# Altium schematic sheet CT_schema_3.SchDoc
size 287 x 169 mm
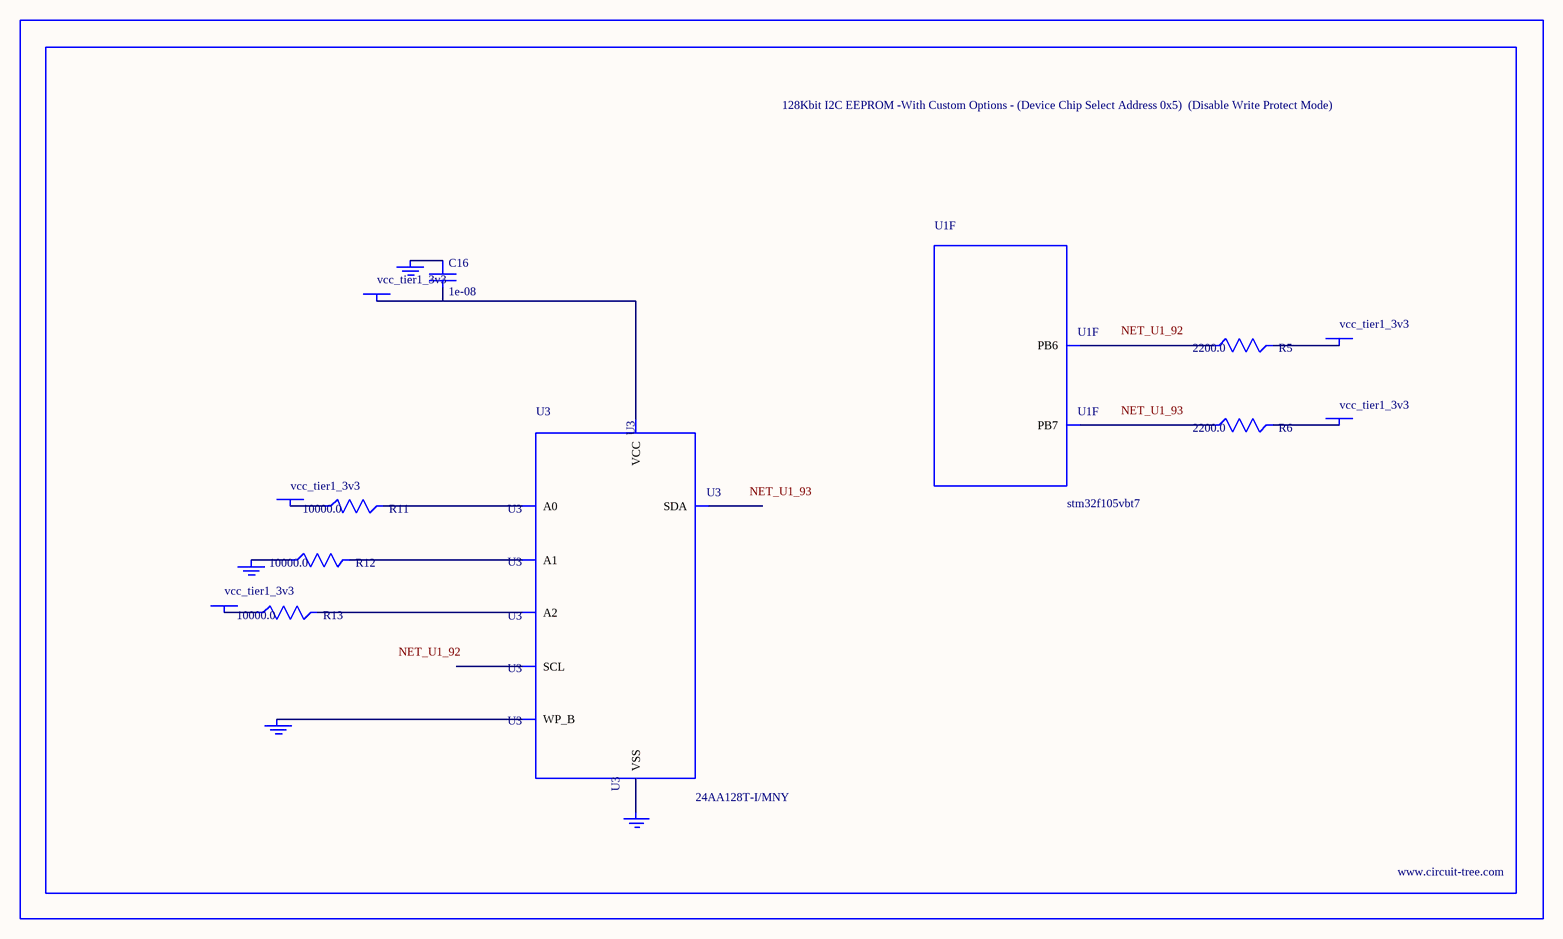
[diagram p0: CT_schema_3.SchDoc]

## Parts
BORDER2  (no value)
C16  1e-08  [C0402]
GND_INSTANCE_2_0  (no value)
GND_INSTANCE_2_1  (no value)
GND_INSTANCE_2_2  (no value)
GND_INSTANCE_2_3  (no value)
POWER_INSTANCE_2_0  vcc_tier1_3v3
POWER_INSTANCE_2_1  vcc_tier1_3v3
POWER_INSTANCE_2_2  vcc_tier1_3v3
POWER_INSTANCE_2_3  vcc_tier1_3v3
POWER_INSTANCE_2_4  vcc_tier1_3v3
R5  2200.0  [R0603]
R6  2200.0  [R0603]
R11  10000.0  [R0603]
R12  10000.0  [R0603]
R13  10000.0  [R0603]
U1  stm32f105vbt7  [LQFP100]  (part F of 10)
U3  24AA128T-I/MNY  [TDFN-8/6MM]

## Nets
NetC16_1: C16.1 GND_INSTANCE_2_2.0(GND)
NetC16_2: C16.2 POWER_INSTANCE_2_2.0(PWR) U3.8(VCC)
NetGND_INSTANCE_2_0_0: GND_INSTANCE_2_0.0(GND) R12.1
NetGND_INSTANCE_2_1_0: GND_INSTANCE_2_1.0(GND) U3.7(WP_B)
NetGND_INSTANCE_2_3_0: GND_INSTANCE_2_3.0(GND) U3.4(VSS)
NetPOWER_INSTANCE_2_0_0: POWER_INSTANCE_2_0.0(PWR) R11.1
NetPOWER_INSTANCE_2_1_0: POWER_INSTANCE_2_1.0(PWR) R13.1
NetPOWER_INSTANCE_2_3_0: POWER_INSTANCE_2_3.0(PWR) R5.2
NetPOWER_INSTANCE_2_4_0: POWER_INSTANCE_2_4.0(PWR) R6.2
NetR5_1: R5.1 U1.92(PB6)
NetR6_1: R6.1 U1.93(PB7)
NetR11_2: R11.2 U3.1(A0)
NetR12_2: R12.2 U3.2(A1)
NetR13_2: R13.2 U3.3(A2)

Not connected (* = marked no-connect by the designer): U3 5(SDA) 6(SCL)

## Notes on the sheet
- Labels drawn without touching a wire or pin: NET_U1_92, NET_U1_93

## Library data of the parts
BORDER2 = BORDER_PAGE2
C16 = C0402C103K3RAC
GND_INSTANCE_2_0-GND_INSTANCE_2_3 = GND
POWER_INSTANCE_2_0-POWER_INSTANCE_2_4 = PWR
R5 R6 = RC0603JR-072K2L
R11-R13 = RC0603JR-0710KL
